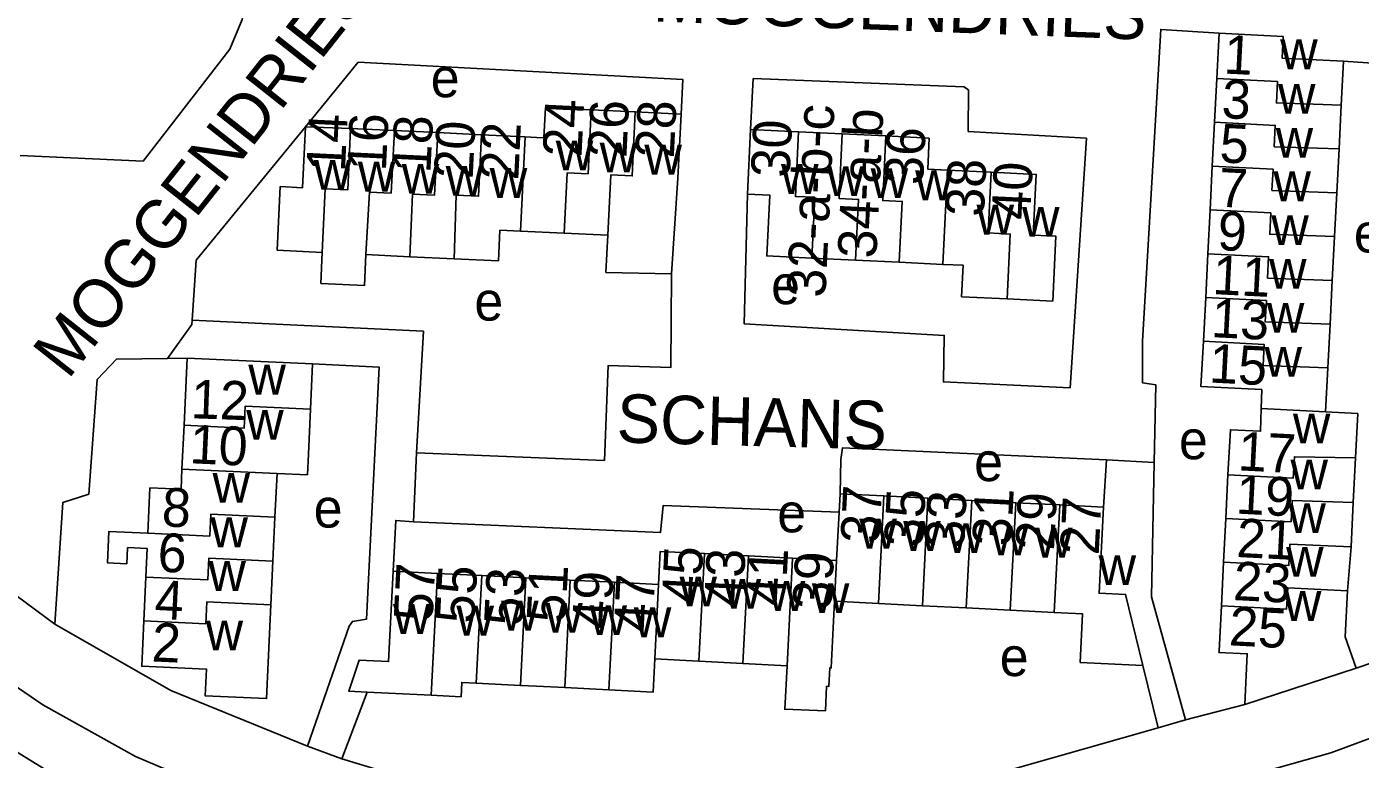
# Model space of a CAD drawing. Extents: x 163026 to 166241, y 382475 to 384501.
# Drawn here: x 164447.4 to 164584.9, y 383524.4 to 383599.9 of the extents above; entities that cross this region are included whole.
import ezdxf

# ---------------------------------------------------------------- set-up
doc = ezdxf.new("R2010")
doc.units = 0
for name, color, linetype in [('BLT_Basislijn', 7, 'Continuous'), ('BLT_Bebouwing', 7, 'Continuous'), ('BLT_Centroide', 7, 'Continuous'), ('BLT_Huisnummer', 7, 'Continuous'), ('BLT_Huisnummer_ tussenligend', 7, 'Continuous'), ('BLT_Huisnummer_reeks', 7, 'Continuous'), ('BLT_Onderverdeling_panden', 7, 'Continuous'), ('BLT_Straatnaam', 7, 'Continuous')]:
    doc.layers.add(name, color=color, linetype=linetype)

msp = doc.modelspace()

# ---------------------------------------------------------------- linework, layer by layer
at = {"layer": 'BLT_Basislijn'}
for p, q in [((164463.96, 383565.76), (164461.93, 383565.73)), ((164487.29, 383548.88), (164487.62, 383556)), ((164558.45, 383550.38), (164558.77, 383555.27)), ((164563.66, 383554.99), (164558.77, 383555.27)), ((164440.32, 383545.69), (164450.31, 383538.33)), ((164584.51, 383533.77), (164598.35, 383538.59)), ((164566.91, 383528.46), (164573.02, 383530.03)), ((164564.07, 383527.62), (164566.91, 383528.46)), ((164476.37, 383525.74), (164479.91, 383524.43))]:
    msp.add_line(p, q, dxfattribs=at)
for points in [[(164316.74, 383637.52), (164399.59, 383569.15), (164439.68, 383536.44), (164449.09, 383529.98), (164458.65, 383524.65), (164472.19, 383518.92), (164485.74, 383514.54), (164499.92, 383512), (164504.7, 383511.64), (164519.36, 383511.35), (164533, 383512.62), (164547.18, 383515.25), (164581.89, 383525.04), (164642.18, 383547.36), (164693.59, 383567.42), (164700, 383570.19), (164761.7, 383597.42), (164778.75, 383605.71), (164783.1, 383609.13), (164785.13, 383612.46), (164785.97, 383614.66), (164786.37, 383617.55)], [(164446.73, 383586.66), (164459.41, 383586.09), (164468.37, 383597.62), (164469.65, 383600.68), (164470.21, 383603.27), (164470.18, 383606.7), (164469.48, 383610.38), (164465.92, 383616.6), (164455.8, 383617.12)], [(164570.37, 383599.26), (164564.36, 383599.66), (164562.46, 383567.49), (164562.46, 383563.22), (164563.83, 383563.01), (164563.66, 383554.99)], [(164476.17, 383589.6), (164481.61, 383596.28), (164515.07, 383594.5), (164514.89, 383590.93)], [(164583.2, 383596.39), (164593.59, 383595.68), (164593.58, 383592.75)], [(164522.05, 383589.34), (164522.34, 383594.59), (164544.06, 383593.75), (164544.54, 383593.43), (164544.51, 383589.15), (164556.68, 383588.43), (164555, 383562.71), (164541.94, 383563.3), (164542.02, 383568.1), (164521.39, 383569.31), (164521.73, 383582.68)], [(164476.17, 383589.6), (164464.9, 383575.87), (164464.47, 383569.67)], [(164487.62, 383556), (164506.98, 383555.2), (164507.38, 383565.01), (164513.83, 383564.78), (164513.9, 383574.44)], [(164464.47, 383569.67), (164464.43, 383569.24), (164461.93, 383565.73)], [(164487.62, 383556), (164488.32, 383568.53), (164464.47, 383569.67)], [(164450.31, 383538.33), (164451.16, 383550.88), (164453.82, 383551.73), (164454.7, 383563.55), (164456.67, 383565.66), (164461.93, 383565.73)], [(164476.89, 383565.16), (164483.75, 383564.83), (164482.46, 383538.84), (164481, 383538.6), (164480.68, 383538.12), (164476.37, 383525.74)], [(164531.28, 383551.77), (164531.36, 383555.29), (164531.53, 383556.49), (164558.77, 383555.27)], [(164566.91, 383528.46), (164563.41, 383541.12), (164563.66, 383554.99)], [(164531.18, 383549.86), (164513.05, 383550.56), (164512.76, 383547.76), (164487.29, 383548.88)], [(164487.29, 383548.88), (164485.47, 383549.01), (164485.21, 383543.77)], [(164450.31, 383538.33), (164462.29, 383531.49), (164476.37, 383525.74)], [(164562.51, 383534.04), (164564.07, 383527.62)], [(164482.51, 383531.31), (164479.91, 383524.43)], [(164440.27, 383528.91), (164456.96, 383518.6), (164467.83, 383513.21), (164475.76, 383510.06), (164493.55, 383504.89), (164510.37, 383502.9), (164515.06, 383502.82)], [(164479.91, 383524.43), (164491.95, 383520.78), (164504.22, 383519.08), (164509.86, 383518.76), (164521.75, 383518.84), (164533.16, 383519.96), (164545.59, 383522.35), (164564.07, 383527.62)]]:
    msp.add_lwpolyline(points, dxfattribs=at)
at = {"layer": 'BLT_Bebouwing'}
for p, q in [((164570.14, 383594.61), (164570.37, 383599.26)), ((164583.2, 383596.39), (164582.97, 383591.86)), ((164569.9, 383590.08), (164570.14, 383594.61)), ((164582.97, 383591.86), (164582.74, 383587.34)), ((164510.17, 383591.16), (164514.89, 383590.93)), ((164569.67, 383585.56), (164569.9, 383590.08)), ((164476.17, 383589.6), (164480.82, 383589.45)), ((164480.82, 383589.45), (164485.33, 383589.23)), ((164485.33, 383589.23), (164489.82, 383589.02)), ((164489.82, 383589.02), (164494.31, 383588.8)), ((164494.31, 383588.8), (164498.81, 383588.58)), ((164522.05, 383589.34), (164521.73, 383582.68)), ((164527.01, 383589.1), (164522.05, 383589.34)), ((164531.51, 383588.89), (164527.01, 383589.1)), ((164498.81, 383588.58), (164500, 383588.53)), ((164582.74, 383587.34), (164582.5, 383582.82)), ((164546.86, 383584.94), (164542.36, 383585.15)), ((164569.44, 383581.05), (164569.67, 383585.56)), ((164582.5, 383582.82), (164582.27, 383578.3)), ((164569.22, 383576.53), (164569.44, 383581.05)), ((164498.34, 383578.87), (164496.21, 383578.97)), ((164502.84, 383578.65), (164498.34, 383578.87)), ((164507.34, 383578.43), (164502.84, 383578.65)), ((164582.27, 383578.3), (164582.04, 383573.78)), ((164486.93, 383576.22), (164482.37, 383576.44)), ((164568.99, 383572.01), (164569.22, 383576.53)), ((164491.49, 383576), (164486.93, 383576.22)), ((164528.38, 383576.08), (164532.89, 383575.86)), ((164532.89, 383575.86), (164537.39, 383575.65)), ((164537.39, 383575.65), (164541.89, 383575.43)), ((164541.89, 383575.43), (164543.97, 383575.34)), ((164582.04, 383573.78), (164581.81, 383569.26)), ((164568.76, 383567.5), (164568.99, 383572.01)), ((164581.81, 383569.26), (164581.58, 383564.74)), ((164476.89, 383565.16), (164463.96, 383565.76)), ((164476.68, 383560.5), (164476.89, 383565.16)), ((164581.58, 383564.74), (164581.35, 383560.21)), ((164476.46, 383555.85), (164476.68, 383560.5)), ((164463.64, 383558.83), (164463.43, 383554.31)), ((164584.44, 383555.46), (164584.2, 383550.88)), ((164473.02, 383549.34), (164473.23, 383553.86)), ((164571.05, 383549.22), (164571.28, 383553.72)), ((164459.92, 383547.7), (164460.13, 383552.38)), ((164531.18, 383549.86), (164531.28, 383551.77)), ((164531.28, 383551.77), (164535.81, 383551.54)), ((164535.81, 383551.54), (164540.34, 383551.31)), ((164540.34, 383551.31), (164544.87, 383551.08)), ((164544.87, 383551.08), (164549.4, 383550.84)), ((164549.4, 383550.84), (164553.93, 383550.61)), ((164553.93, 383550.61), (164558.45, 383550.38)), ((164584.2, 383550.88), (164583.97, 383546.3)), ((164472.81, 383544.82), (164473.02, 383549.34)), ((164530.93, 383544.89), (164531.18, 383549.86)), ((164570.83, 383544.72), (164571.05, 383549.22)), ((164583.97, 383546.3), (164583.62, 383541.77)), ((164472.6, 383540.31), (164472.81, 383544.82)), ((164517.29, 383545.59), (164521.84, 383545.35)), ((164521.84, 383545.35), (164526.39, 383545.12)), ((164526.39, 383545.12), (164530.93, 383544.89)), ((164570.6, 383540.22), (164570.83, 383544.72)), ((164489.77, 383543.55), (164485.21, 383543.77)), ((164494.34, 383543.32), (164489.77, 383543.55)), ((164498.9, 383543.1), (164494.34, 383543.32)), ((164459.71, 383543.18), (164459.48, 383538.66)), ((164500, 383543.04), (164498.9, 383543.1)), ((164500, 383543.04), (164503.46, 383542.87)), ((164503.46, 383542.87), (164508.02, 383542.64)), ((164508.02, 383542.64), (164512.57, 383542.4)), ((164535.24, 383540.45), (164530.72, 383540.68)), ((164539.77, 383540.22), (164535.24, 383540.45)), ((164544.3, 383539.99), (164539.77, 383540.22)), ((164548.83, 383539.76), (164544.3, 383539.99)), ((164553.36, 383539.53), (164548.83, 383539.76)), ((164516.73, 383534.5), (164512.18, 383534.73)), ((164521.27, 383534.27), (164516.73, 383534.5)), ((164525.82, 383534.03), (164521.27, 383534.27)), ((164584.51, 383533.77), (164573.02, 383530.03)), ((164482.51, 383531.31), (164489.14, 383530.98)), ((164493.77, 383532.23), (164498.33, 383532)), ((164498.33, 383532), (164500, 383531.91)), ((164502.89, 383531.77), (164500, 383531.91)), ((164507.45, 383531.53), (164502.89, 383531.77))]:
    msp.add_line(p, q, dxfattribs=at)
for points in [[(164570.37, 383599.26), (164576.99, 383598.92), (164576.87, 383596.71), (164583.2, 383596.39)], [(164500.75, 383588.49), (164500.9, 383591.6), (164505.61, 383591.37)], [(164505.61, 383591.37), (164510.17, 383591.16)], [(164514.89, 383590.93), (164514.57, 383584.32), (164513.9, 383574.44)], [(164477.9, 383576.65), (164473.25, 383576.88), (164473.57, 383583.45), (164475.87, 383583.33), (164476.17, 383589.6)], [(164536.01, 383588.67), (164531.51, 383588.89)], [(164540.49, 383588.46), (164536.01, 383588.67)], [(164500, 383588.53), (164500.75, 383588.49)], [(164542.36, 383585.15), (164540.34, 383585.24), (164540.49, 383588.46)], [(164548.51, 383571.86), (164553.21, 383571.64), (164553.53, 383578.34), (164551.21, 383578.45), (164551.51, 383584.71), (164546.86, 383584.94)], [(164521.73, 383582.68), (164524.03, 383582.57), (164523.73, 383576.3), (164528.38, 383576.08)], [(164496.21, 383578.97), (164496.05, 383575.78), (164491.49, 383576)], [(164513.9, 383574.44), (164507.15, 383574.59), (164507.34, 383578.43)], [(164482.37, 383576.44), (164482.26, 383573.25), (164477.75, 383573.46), (164477.9, 383576.65)], [(164543.97, 383575.34), (164543.81, 383572.09), (164548.51, 383571.86)], [(164574.72, 383560.55), (164574.77, 383562.51), (164568.5, 383562.83), (164568.76, 383567.5)], [(164463.96, 383565.76), (164463.64, 383558.83)], [(164571.28, 383553.72), (164571.53, 383558.37), (164574.65, 383558.21), (164574.72, 383560.55)], [(164581.35, 383560.21), (164584.67, 383560.04), (164584.44, 383555.46)], [(164473.23, 383553.86), (164476.36, 383553.72), (164476.46, 383555.85)], [(164463.43, 383554.31), (164463.33, 383552.23), (164460.13, 383552.38)], [(164558.45, 383550.38), (164558, 383541.5), (164560.72, 383541.38), (164562.51, 383534.04)], [(164459.92, 383547.7), (164455.9, 383547.89), (164455.75, 383544.64), (164457.74, 383544.55), (164457.82, 383546.22), (164459.84, 383546.12), (164459.71, 383543.18)], [(164512.57, 383542.4), (164512.75, 383545.82), (164517.29, 383545.59)], [(164485.21, 383543.77), (164484.74, 383534.46), (164481.71, 383534.62), (164480.62, 383531.4), (164482.51, 383531.31)], [(164530.72, 383540.68), (164530.37, 383533.8), (164530.23, 383533.81), (164530.14, 383531.9), (164529.89, 383531.91), (164529.78, 383529.36), (164525.58, 383529.54), (164525.82, 383534.03)], [(164583.62, 383541.77), (164583.37, 383537.01), (164584.51, 383533.77)], [(164459.48, 383538.66), (164459.28, 383533.98), (164465.96, 383533.67), (164465.81, 383530.94), (164472.16, 383530.64), (164472.6, 383540.31)], [(164562.51, 383534.04), (164556.05, 383534.37), (164556.3, 383539.38), (164553.36, 383539.53)], [(164573.02, 383530.03), (164573.27, 383535.26), (164570.35, 383535.4), (164570.36, 383535.57), (164570.6, 383540.22)], [(164512.18, 383534.73), (164512.01, 383531.3), (164507.45, 383531.53)], [(164489.14, 383530.98), (164492.21, 383530.83), (164492.28, 383532.3), (164493.77, 383532.23)]]:
    msp.add_lwpolyline(points, dxfattribs=at)
at = {"layer": 'BLT_Onderverdeling_panden'}
for p, q in [((164498.34, 383578.87), (164498.81, 383588.58)), ((164541.89, 383575.43), (164542.36, 383585.15)), ((164574.72, 383560.55), (164581.35, 383560.21)), ((164463.43, 383554.31), (164473.23, 383553.86)), ((164535.24, 383540.45), (164535.81, 383551.54)), ((164539.77, 383540.22), (164540.34, 383551.31)), ((164544.3, 383539.99), (164544.87, 383551.08)), ((164548.83, 383539.76), (164549.4, 383550.84)), ((164553.36, 383539.53), (164553.93, 383550.61)), ((164516.73, 383534.5), (164517.29, 383545.59)), ((164521.27, 383534.27), (164521.84, 383545.35)), ((164525.82, 383534.03), (164526.39, 383545.12)), ((164530.72, 383540.68), (164530.93, 383544.89)), ((164489.14, 383530.98), (164489.77, 383543.55)), ((164493.77, 383532.23), (164494.34, 383543.32)), ((164498.33, 383532), (164498.9, 383543.1)), ((164502.89, 383531.77), (164503.46, 383542.87)), ((164507.45, 383531.53), (164508.02, 383542.64)), ((164512.18, 383534.73), (164512.57, 383542.4))]:
    msp.add_line(p, q, dxfattribs=at)
for points in [[(164570.14, 383594.61), (164576.39, 383594.28), (164576.28, 383592.08), (164582.97, 383591.86)], [(164502.84, 383578.65), (164503.14, 383584.87), (164505.3, 383584.77), (164505.61, 383591.37)], [(164507.34, 383578.43), (164507.64, 383584.65), (164509.86, 383584.55), (164510.17, 383591.16)], [(164569.9, 383590.08), (164576.16, 383589.76), (164576.05, 383587.56), (164582.74, 383587.34)], [(164477.9, 383576.65), (164478.21, 383583.22), (164480.52, 383583.11), (164480.82, 383589.45)], [(164482.37, 383576.44), (164482.75, 383582.89), (164484.99, 383582.78), (164485.33, 383589.23)], [(164486.93, 383576.22), (164487.21, 383582.68), (164489.46, 383582.56), (164489.82, 383589.02)], [(164491.49, 383576), (164491.71, 383582.57), (164494.01, 383582.46), (164494.31, 383588.8)], [(164528.38, 383576.08), (164528.68, 383582.35), (164526.68, 383582.44), (164527.01, 383589.1)], [(164532.89, 383575.86), (164533.19, 383582.13), (164531.19, 383582.23), (164531.51, 383588.89)], [(164537.39, 383575.65), (164537.69, 383581.92), (164535.69, 383582.01), (164536.01, 383588.67)], [(164548.51, 383571.86), (164548.83, 383578.56), (164546.56, 383578.67), (164546.86, 383584.94)], [(164569.67, 383585.56), (164575.93, 383585.24), (164575.82, 383583.05), (164582.5, 383582.82)], [(164569.44, 383581.05), (164575.7, 383580.73), (164575.59, 383578.53), (164582.27, 383578.3)], [(164569.22, 383576.53), (164575.47, 383576.21), (164575.36, 383574.02), (164582.04, 383573.78)], [(164568.99, 383572.01), (164575.24, 383571.7), (164575.13, 383569.5), (164581.81, 383569.26)], [(164568.76, 383567.5), (164575.01, 383567.18), (164574.9, 383564.98), (164581.58, 383564.74)], [(164463.64, 383558.83), (164469.85, 383558.54), (164469.95, 383560.81), (164476.68, 383560.5)], [(164571.28, 383553.72), (164578.02, 383553.38), (164578.13, 383555.58), (164584.44, 383555.46)], [(164571.05, 383549.22), (164577.79, 383548.88), (164577.9, 383551.08), (164584.2, 383550.88)], [(164459.92, 383547.7), (164466.3, 383547.41), (164466.41, 383549.65), (164473.02, 383549.34)], [(164570.83, 383544.72), (164577.56, 383544.38), (164577.67, 383546.58), (164583.97, 383546.3)], [(164459.71, 383543.18), (164466.09, 383542.88), (164466.2, 383545.13), (164472.81, 383544.82)], [(164570.6, 383540.22), (164577.33, 383539.88), (164577.44, 383542.08), (164583.62, 383541.77)], [(164459.48, 383538.66), (164465.88, 383538.36), (164465.99, 383540.61), (164472.6, 383540.31)]]:
    msp.add_lwpolyline(points, dxfattribs=at)

# ---------------------------------------------------------------- texts
at = {"layer": 'BLT_Centroide'}
for s, p in [('w', (164576.67, 383595.56)), ('e', (164489.08, 383592.67)), ('w', (164576.44, 383590.97)), ('w', (164576.2, 383586.44)), ('w', (164501.97, 383585.12)), ('w', (164506.5, 383584.91)), ('w', (164511.11, 383584.69)), ('w', (164477.03, 383583.12)), ('w', (164481.56, 383582.94)), ('w', (164486.09, 383582.72)), ('w', (164490.62, 383582.5)), ('w', (164495.16, 383582.28)), ('w', (164525.2, 383582.7)), ('w', (164529.94, 383582.48)), ('w', (164534.44, 383582.27)), ('w', (164539.03, 383582.05)), ('w', (164575.97, 383581.94)), ('w', (164545.36, 383578.5)), ('w', (164550.05, 383578.28)), ('w', (164575.75, 383577.41)), ('e', (164584.26, 383576.66)), ('w', (164575.52, 383572.91)), ('e', (164524.18, 383571.32)), ('e', (164493.58, 383569.63)), ('w', (164575.29, 383568.38)), ('w', (164575.05, 383563.84)), ('w', (164470.27, 383562)), ('w', (164470.05, 383557.34)), ('w', (164577.98, 383556.97)), ('e', (164566.23, 383555.33)), ('e', (164545.11, 383553.07)), ('w', (164577.73, 383552.22)), ('w', (164466.58, 383550.84)), ('e', (164477.01, 383548.28)), ('e', (164524.81, 383547.79)), ('w', (164577.51, 383547.72)), ('w', (164466.36, 383546.25)), ('w', (164533.27, 383546.11)), ('w', (164537.8, 383545.88)), ('w', (164542.33, 383545.66)), ('w', (164546.84, 383545.42)), ('w', (164551.38, 383545.19)), ('w', (164577.28, 383543.22)), ('w', (164466.15, 383541.75)), ('w', (164557.94, 383542.34)), ('w', (164514.73, 383540.16)), ('w', (164519.28, 383539.92)), ('w', (164523.83, 383539.69)), ('w', (164528.38, 383539.47)), ('w', (164496.33, 383537.66)), ('w', (164577.05, 383538.66)), ('w', (164485.2, 383537.31)), ('w', (164491.73, 383537.14)), ('w', (164500.89, 383537.44)), ('w', (164505.45, 383537.19)), ('w', (164510.02, 383536.97)), ('w', (164465.87, 383535.62)), ('e', (164547.75, 383532.96))]:
    msp.add_text(s, height=4, dxfattribs=at).set_placement(p)
at = {"layer": 'BLT_Huisnummer'}
for s, rotation, p in [('1', 357.0674, (164570.79, 383595.12)), ('28', 87.2452, (164514.14, 383586.33)), ('14', 87.2452, (164480.23, 383584.92)), ('18', 87.2452, (164489.04, 383584.79)), ('30', 87.272, (164526.07, 383584.32)), ('22', 87.2452, (164498.1, 383584.06)), ('5', 357.0674, (164570.36, 383585.96)), ('40', 87.2733, (164550.88, 383579.97)), ('9', 357.0674, (164570.14, 383576.92)), ('15', 357.0674, (164569.28, 383563.25)), ('12', 357.9645, (164464.3, 383559.56)), ('17', 357.0674, (164572.24, 383554.19)), ('35', 87.0816, (164539.81, 383546.23)), ('31', 87.0816, (164548.9, 383546.31)), ('27', 87.0816, (164557.95, 383545.39)), ('21', 357.0674, (164572.1, 383545.25)), ('6', 357.3444, (164460.85, 383543.74)), ('43', 87.0816, (164521.25, 383540.08)), ('39', 87.0816, (164530.37, 383539.76)), ('57', 87.0816, (164489.25, 383538.56)), ('51', 87.0816, (164502.95, 383538.42)), ('47', 87.0816, (164511.93, 383537.43)), ('25', 357.0674, (164571.33, 383536.14)), ('2', 357.3444, (164460.25, 383534.48))]:
    msp.add_text(s, height=4, rotation=rotation, dxfattribs=at).set_placement(p)
at = {"layer": 'BLT_Huisnummer_ tussenligend'}
for s, rotation, p in [('3', 357.0674, (164570.57, 383590.53)), ('24', 87.2452, (164504.62, 383586.44)), ('26', 87.2452, (164509.25, 383586.36)), ('16', 87.2452, (164484.45, 383584.99)), ('20', 87.2452, (164493.4, 383584.2)), ('36', 87.2653, (164539.83, 383583.57)), ('38', 87.2653, (164546.1, 383580.3)), ('7', 357.0674, (164570.24, 383581.39)), ('11', 357.0674, (164569.63, 383572.37)), ('13', 357.0674, (164569.5, 383567.93)), ('10', 357.3444, (164464.16, 383554.92)), ('19', 357.0674, (164572.04, 383549.73)), ('8', 357.3444, (164461.29, 383548.42)), ('37', 87.0816, (164535.32, 383546.58)), ('33', 87.0816, (164544.05, 383546.05)), ('29', 87.0816, (164553.34, 383545.88)), ('45', 87.0816, (164516.88, 383540.32)), ('41', 87.0816, (164525.64, 383540.13)), ('23', 357.0674, (164571.76, 383540.81)), ('55', 87.0816, (164493.58, 383538.34)), ('53', 87.0816, (164498.56, 383538.1)), ('49', 87.0816, (164507.63, 383537.75)), ('4', 357.3444, (164460.55, 383538.88))]:
    msp.add_text(s, height=4, rotation=rotation, dxfattribs=at).set_placement(p)
at = {"layer": 'BLT_Huisnummer_reeks'}
for s, rotation, p in [('32-a-b-c', 87.272, (164529.77, 383571.95)), ('34-a-b', 87.25, (164535.02, 383575.99))]:
    msp.add_text(s, height=4, rotation=rotation, dxfattribs=at).set_placement(p)
at = {"layer": 'BLT_Straatnaam'}
for s, rotation, p in [('MOGGENDRIES', 51.6772, (164451.68, 383563.46)), ('MOGGENDRIES', 357.8669, (164511.95, 383600.49)), ('SCHANS', 358.4529, (164508.21, 383557.07))]:
    msp.add_text(s, height=5, rotation=rotation, dxfattribs=at).set_placement(p)

doc.saveas('drawing.dxf')
